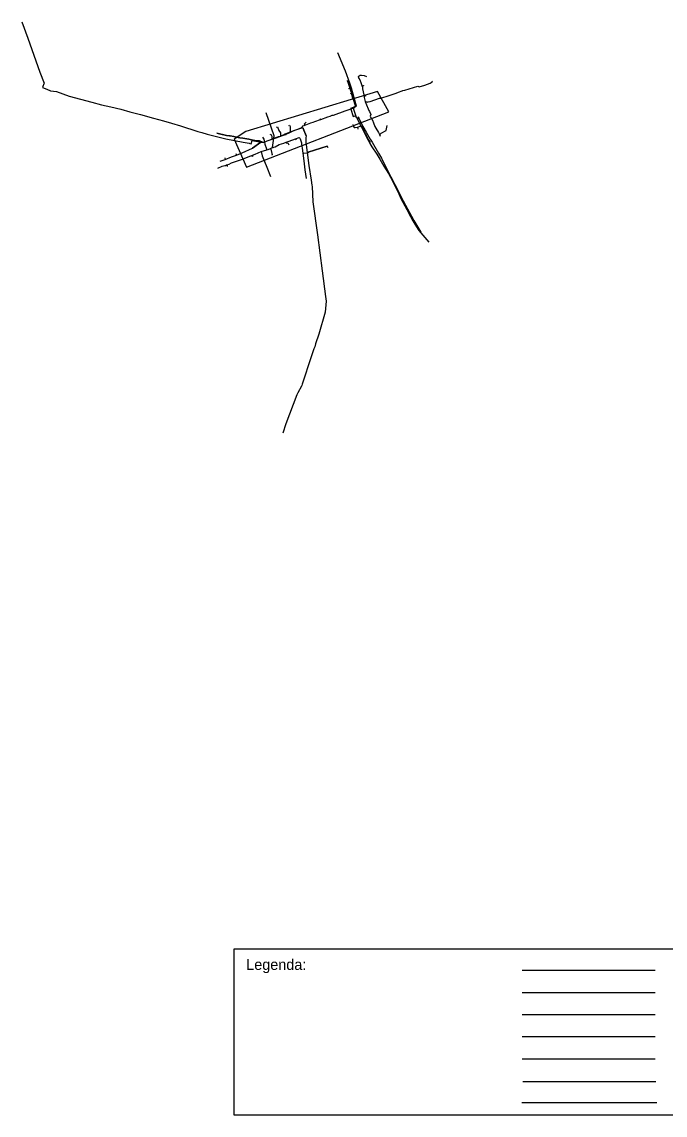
# Model space of a CAD drawing. Extents: x -703329 to -700959, y -1023502 to -1021827.
# Drawn here: x -703329 to -702432, y -1023352 to -1021827 of the extents above; entities that cross this region are included whole.
import ezdxf

# ---------------------------------------------------------------- set-up
doc = ezdxf.new("R2010")
doc.units = 0
for name, color, linetype in [('Vrstva 1', 7, 'Continuous'), ('Vrstva 2', 7, 'Continuous'), ('Vrstva 4', 7, 'Continuous'), ('Vrstva 63', 7, 'Continuous')]:
    doc.layers.add(name, color=color, linetype=linetype)

msp = doc.modelspace()

# ---------------------------------------------------------------- linework, layer by layer
at = {"layer": 'Vrstva 1'}
for p, q in [((-702631.5, -1023149.8), (-702446.1, -1023149.8)), ((-702631.5, -1023180.6), (-702446.1, -1023180.6)), ((-702631.5, -1023211.3), (-702446.1, -1023211.3)), ((-702631.5, -1023242), (-702446.1, -1023242)), ((-702631.5, -1023273.4), (-702446.1, -1023273.4)), ((-702630.5, -1023304.9), (-702445.1, -1023304.9)), ((-702631.7, -1023334.3), (-702443.7, -1023334.3))]:
    msp.add_line(p, q, dxfattribs=at)
for points in [[(-703328.6, -1021827.1), (-703320.4, -1021850), (-703303.8, -1021897.1), (-703297.8, -1021912.8), (-703298, -1021913.4), (-703299.6, -1021917.1), (-703300.1, -1021918.5), (-703293.9, -1021921), (-703288.7, -1021923.3), (-703280.4, -1021924.1), (-703262.9, -1021930.5), (-703231.3, -1021939.3), (-703217.5, -1021942.7), (-703204.7, -1021945.5), (-703190.7, -1021948.9), (-703178, -1021952.5), (-703172.5, -1021954.1), (-703163.3, -1021956.5), (-703145, -1021961.4), (-703131.4, -1021965.2), (-703119.9, -1021968.3), (-703107.6, -1021972.3), (-703083.5, -1021979.9), (-703077.9, -1021981.4), (-703070.4, -1021983.5), (-703057.2, -1021987.1), (-703044.3, -1021990), (-703032.5, -1021992.5), (-703020.3, -1021994.8), (-703011.7, -1021996.5)], [(-702859.8, -1021903.5), (-702857.1, -1021901.2), (-702855.5, -1021901.3), (-702851.6, -1021901.9), (-702848.5, -1021903.2)], [(-702859.8, -1021903.5), (-702859.2, -1021905.9), (-702857.5, -1021907.9), (-702856.1, -1021911.8), (-702855.9, -1021912.9), (-702854.8, -1021915.9), (-702854.7, -1021916.3)], [(-702875.2, -1021909.1), (-702873.9, -1021912.8), (-702872.1, -1021918.2), (-702871.5, -1021919.8), (-702870.5, -1021923), (-702869.2, -1021926.6)], [(-702873.9, -1021912.8), (-702872.1, -1021918.2)], [(-702871.5, -1021919.8), (-702870.5, -1021923)], [(-702855.9, -1021912.9), (-702854.8, -1021915.9)], [(-702854.7, -1021916.3), (-702852.8, -1021915.7), (-702851.9, -1021916.1)], [(-702854.7, -1021916.3), (-702854.1, -1021918.2), (-702854.1, -1021920.4), (-702852.1, -1021928.9), (-702851.9, -1021930.3), (-702851.8, -1021930.8)], [(-702848, -1021938.4), (-702846.7, -1021938.9), (-702845.8, -1021938.8), (-702843, -1021938), (-702830.3, -1021933.6), (-702828.2, -1021933.3), (-702816.9, -1021929.8), (-702806.9, -1021926.6), (-702803.7, -1021925), (-702798.6, -1021923.5), (-702797.5, -1021922.8), (-702795.1, -1021922.5), (-702776.6, -1021917), (-702775, -1021917.6), (-702767.2, -1021915.4), (-702759.6, -1021912.6), (-702756.7, -1021910.7), (-702756.5, -1021910.6), (-702756.8, -1021909.7)], [(-702912.3, -1021963.2), (-702911.9, -1021963.2), (-702902.2, -1021959.6), (-702898.9, -1021958.5), (-702897, -1021957.8), (-702896, -1021957), (-702894.5, -1021957), (-702878, -1021951.2), (-702864.7, -1021946.5), (-702863.6, -1021944.4), (-702866.3, -1021935.5)], [(-702870.5, -1021927), (-702869.2, -1021926.6)], [(-702866.3, -1021935.5), (-702867.2, -1021933.5), (-702868.1, -1021930.2), (-702869.2, -1021926.6)], [(-702868.1, -1021930.2), (-702867.2, -1021933.5)], [(-702851.8, -1021930.8), (-702848.6, -1021929.8)], [(-702851.8, -1021930.8), (-702851.6, -1021932.5), (-702850, -1021938.1)], [(-702850, -1021938.1), (-702849.5, -1021940.3), (-702845, -1021950.5), (-702844.2, -1021952.1), (-702842.4, -1021956.3), (-702843.3, -1021958.5), (-702842.6, -1021960.2), (-702841.9, -1021960.8)], [(-702850, -1021938.1), (-702848, -1021938.4)], [(-702849.5, -1021940.3), (-702845, -1021950.5)], [(-702934.1, -1021971.1), (-702934.8, -1021969.5), (-702932.5, -1021967.1)], [(-702934.1, -1021971.1), (-702932.8, -1021970.6), (-702925.8, -1021968.1), (-702922.6, -1021967), (-702920.5, -1021966.2), (-702912.3, -1021963.2)], [(-702922.6, -1021967), (-702920.5, -1021966.2)], [(-702912.9, -1021961.7), (-702912.3, -1021963.2)], [(-702902.2, -1021959.6), (-702898.9, -1021958.5)], [(-702841.9, -1021960.8), (-702841.2, -1021960.7)], [(-702841.9, -1021960.8), (-702840.2, -1021964.1)], [(-702841.9, -1021960.8), (-702840.2, -1021964.1), (-702838.5, -1021967.8), (-702836.5, -1021972.8), (-702834.1, -1021977.7), (-702832.8, -1021979.1), (-702831.5, -1021981.3), (-702830.4, -1021984.4)], [(-703054.9, -1021983), (-703056.8, -1021982.4)], [(-703056.8, -1021982.4), (-703054.9, -1021983)], [(-703049.6, -1021984.3), (-703054.9, -1021983)], [(-703054.9, -1021983), (-703049.6, -1021984.3)], [(-703049.6, -1021984.3), (-703049.4, -1021983.4)], [(-702986.6, -1021993.1), (-702985.4, -1021992.5), (-702980, -1021990.5), (-702974.4, -1021988.6), (-702968.9, -1021986.8), (-702960.4, -1021983.7), (-702955.2, -1021981.2), (-702952.3, -1021979.8)], [(-702973.7, -1021973.8), (-702972.6, -1021973.4), (-702970.4, -1021978.6), (-702968.4, -1021981.7), (-702968.2, -1021986.3)], [(-702948.3, -1021978.3), (-702937.2, -1021974.2), (-702936.5, -1021975.8), (-702932.5, -1021986.1), (-702933.1, -1021989), (-702932.7, -1021994.8), (-702928.7, -1022027.6), (-702925.5, -1022048), (-702924.4, -1022054.9), (-702924.1, -1022056.7), (-702923.3, -1022078.1), (-702916.8, -1022124.2), (-702910.2, -1022174.3), (-702905.4, -1022210.2), (-702904.4, -1022216.6), (-702906.1, -1022232), (-702914.8, -1022262.8), (-702919.3, -1022276.1), (-702920.5, -1022280.2), (-702921.6, -1022283.3), (-702925.4, -1022294.4), (-702937.8, -1022332.5), (-702938.3, -1022334.1), (-702938.8, -1022335.4), (-702943.9, -1022344.7), (-702945.3, -1022347.2), (-702960.7, -1022387.9), (-702965.1, -1022400.9)], [(-702962.6, -1021983.8), (-702961.8, -1021983.4)], [(-702961.8, -1021983.4), (-702955.2, -1021980.8)], [(-702961.8, -1021983.4), (-702961.2, -1021984.9)], [(-702956.7, -1021971.6), (-702955.6, -1021971.2), (-702954.8, -1021973.2), (-702954.8, -1021976.3), (-702954.7, -1021978.5), (-702955.2, -1021980.8)], [(-702955.2, -1021980.8), (-702949.7, -1021978.6), (-702945.6, -1021977), (-702939.4, -1021975), (-702937.6, -1021973.7), (-702937.4, -1021972.5), (-702937.3, -1021972.2), (-702935.4, -1021971.6), (-702934.1, -1021971.1)], [(-702955.2, -1021980.8), (-702949.7, -1021978.6)], [(-702952.3, -1021979.8), (-702948.3, -1021978.3)], [(-702932.5, -1021986.1), (-702936.5, -1021975.8)], [(-702934.1, -1021971.1), (-702935.4, -1021971.6)], [(-702932.8, -1021970.6), (-702934.1, -1021971.1)], [(-702867.5, -1021970.1), (-702866.7, -1021972), (-702865.7, -1021974.2), (-702864.1, -1021974.5), (-702860.7, -1021974.1)], [(-702860.7, -1021974.1), (-702855.8, -1021972.1)], [(-702860.7, -1021974.1), (-702860.3, -1021976.6)], [(-702855.8, -1021972.1), (-702845.2, -1021992.5), (-702843.2, -1021995.4)], [(-702831.5, -1021981.3), (-702830.4, -1021984.4)], [(-702830.4, -1021984.4), (-702829, -1021983.4), (-702827.8, -1021982.4), (-702820.8, -1021978.5), (-702819.7, -1021971.6)], [(-703039.4, -1021986), (-703043.4, -1021985.4), (-703049.1, -1021984.4), (-703049.6, -1021984.3)], [(-703049.6, -1021984.3), (-703049.1, -1021984.4), (-703043.4, -1021985.4), (-703039.4, -1021986)], [(-703039.4, -1021986), (-703039.2, -1021985.3)], [(-703029.5, -1021987.9), (-703033.1, -1021987.2), (-703038.4, -1021986.2), (-703039.4, -1021986)], [(-703039.4, -1021986), (-703038.4, -1021986.2), (-703033.1, -1021987.2), (-703029.5, -1021987.9)], [(-703029.6, -1022012.9), (-703021.4, -1022009.6), (-703007.3, -1022003.4), (-702995.4, -1021995), (-702993.5, -1021995)], [(-703029.5, -1021987.9), (-703029.4, -1021987.1)], [(-703029.5, -1021987.9), (-703024.7, -1021988.7), (-703020.7, -1021989.4), (-703015.3, -1021990.4)], [(-703015.3, -1021990.4), (-703020.7, -1021989.4), (-703024.7, -1021988.7), (-703029.5, -1021987.9)], [(-703015.3, -1021990.4), (-703015.1, -1021989.6)], [(-703015.3, -1021990.4), (-703012.4, -1021990.9), (-703008.4, -1021991.7), (-703001.5, -1021993), (-702997.6, -1021992.8), (-702993.5, -1021995)], [(-702993.5, -1021995), (-702997.6, -1021992.8), (-703001.5, -1021993), (-703008.4, -1021991.7), (-703012.4, -1021990.9), (-703015.3, -1021990.4)], [(-703011.7, -1021996.5), (-703011, -1021996.6)], [(-703011, -1021996.6), (-703009.3, -1021997), (-703007.8, -1021992.4), (-703006.3, -1021992.6)], [(-702995.4, -1021995), (-703007.3, -1022003.4)], [(-703006.3, -1021992.6), (-703005.5, -1021992.8)], [(-703005.5, -1021992.8), (-702996.9, -1021994.4), (-702991.6, -1021995.2), (-702986.6, -1021993.1)], [(-702993.5, -1021995), (-702992.9, -1021995.2), (-702992.3, -1021995)], [(-702993.3, -1021987.9), (-702991.5, -1021990.6), (-702990.3, -1021995)], [(-702992.3, -1021995), (-702990.7, -1021995)], [(-702990.7, -1021995), (-702990.3, -1021995)], [(-702990.7, -1021995), (-702990.1, -1021997.8), (-702987.7, -1022004), (-702987.2, -1022005.5)], [(-702990.3, -1021995), (-702987.6, -1021993.6), (-702986.8, -1021993.2), (-702984, -1021991.9), (-702980.5, -1021990.6)], [(-702990.3, -1021995), (-702987.6, -1021993.6), (-702986.8, -1021993.2)], [(-702990.1, -1021997.8), (-702987.7, -1022004)], [(-702982.5, -1021984.1), (-702981.5, -1021983.7), (-702980.5, -1021986.4), (-702980.5, -1021990.6)], [(-702980.5, -1021990.6), (-702976.4, -1021989), (-702973.2, -1021988), (-702970.8, -1021987.2)], [(-702975.6, -1022001.4), (-702970.1, -1021998.3), (-702963.5, -1021996.1)], [(-702970.8, -1021987.2), (-702968.2, -1021986.3)], [(-702968.2, -1021986.3), (-702966.3, -1021985.6), (-702963, -1021984.1), (-702962.6, -1021983.8)], [(-702968.2, -1021986.3), (-702966.3, -1021985.6), (-702963, -1021984.1)], [(-702963.5, -1021996.1), (-702960.1, -1021994.7)], [(-702960.1, -1021994.7), (-702956.1, -1021993.5), (-702947.2, -1021990.3)], [(-702960.1, -1021994.7), (-702959.5, -1021996.3), (-702957.8, -1021995.7), (-702956.7, -1021998.6)], [(-702947.2, -1021990.3), (-702942, -1021988.3), (-702941.1, -1021989.1), (-702940.8, -1021990.2), (-702939, -1021995.9), (-702938.9, -1021997.7), (-702938, -1022003.4), (-702937.1, -1022010.4)], [(-702947.2, -1021990.3), (-702946.7, -1021991.6)], [(-702938.9, -1021997.7), (-702938, -1022003.4)], [(-702830.4, -1021984.4), (-702829.2, -1021986.5)], [(-703045.1, -1022018.9), (-703036.6, -1022015.5), (-703029.6, -1022012.9)], [(-703043.3, -1022026.7), (-703039.7, -1022025.5), (-703036.3, -1022023.8), (-703022.7, -1022019), (-703009.7, -1022013.8), (-703007, -1022012.8)], [(-703030.6, -1022010.7), (-703029.6, -1022012.9)], [(-703007.4, -1022015.4), (-703007.6, -1022014.5), (-703006.5, -1022014), (-703007, -1022012.8)], [(-703007, -1022012.8), (-703003.6, -1022011.4), (-702995, -1022008.1)], [(-702995, -1022008.1), (-702987.2, -1022005.5)], [(-702995, -1022008.1), (-702994.5, -1022009.6), (-702993.6, -1022014), (-702990.7, -1022022), (-702987.4, -1022029.8), (-702982, -1022042.7)], [(-702987.2, -1022005.5), (-702985.4, -1022004.9), (-702982.2, -1022003.7)], [(-702982.2, -1022003.7), (-702980.1, -1022002.7), (-702978.2, -1022002.3), (-702977.4, -1022002)], [(-702982.2, -1022003.7), (-702981.8, -1022004.8), (-702979.6, -1022012.6), (-702980.6, -1022013)], [(-702977.6, -1022001.4), (-702977.4, -1022002)], [(-702977.4, -1022002), (-702975.6, -1022001.4)], [(-702937.1, -1022010.4), (-702935.7, -1022010.3), (-702931.2, -1022009.8), (-702929.6, -1022009.6)], [(-702937.1, -1022010.4), (-702935.7, -1022020.8), (-702934.4, -1022033.5), (-702932.6, -1022045.5)], [(-702935.7, -1022010.3), (-702931.2, -1022009.8)], [(-702902.3, -1022002.4), (-702903.2, -1022000.3), (-702929.7, -1022008.8), (-702929.6, -1022009.6)], [(-702929.6, -1022009.6), (-702929.7, -1022008.8), (-702903.2, -1022000.3), (-702902.3, -1022002.4)], [(-703055.6, -1022031), (-703049.3, -1022028.5), (-703045.9, -1022027.5), (-703044.7, -1022027.2), (-703043.3, -1022026.7)], [(-703052.5, -1022021.6), (-703045.1, -1022018.9)], [(-703045.9, -1022016.5), (-703045.1, -1022018.9)], [(-703043.3, -1022026.7), (-703042.7, -1022028.1), (-703042.5, -1022028.8), (-703042.7, -1022028.9)]]:
    msp.add_lwpolyline(points, dxfattribs=at)
msp.add_lwpolyline([(-703033, -1023119.8), (-701813, -1023119.8), (-701813, -1023351.8), (-703033, -1023351.8)], close=True, dxfattribs=at)
at = {"layer": 'Vrstva 2'}
for points in [[(-702888.8, -1021869.8), (-702877.9, -1021895.6), (-702872.1, -1021911.9)], [(-702875.3, -1021908.6), (-702873.9, -1021912.5), (-702871.5, -1021919.4)], [(-702873.6, -1021920.1), (-702871.5, -1021919.4)], [(-702872.1, -1021911.9), (-702869.9, -1021918.9), (-702862.8, -1021944), (-702862.5, -1021944.6), (-702863.9, -1021945)], [(-702871.5, -1021919.4), (-702863.3, -1021944.2), (-702863.6, -1021944.6), (-702863.9, -1021945)], [(-702866.1, -1021946), (-702870.8, -1021947.9), (-702870.4, -1021948.9), (-702867.1, -1021959), (-702867, -1021959.3), (-702864.1, -1021958.3), (-702861.4, -1021961.7), (-702858.8, -1021966.8), (-702855.2, -1021973.9), (-702850.9, -1021982.2), (-702845.8, -1021992), (-702845.4, -1021992.8), (-702844.1, -1021995.9), (-702843.8, -1021996.7), (-702840.8, -1022001.2), (-702834, -1022011.7), (-702829.9, -1022018.6), (-702824, -1022028.3), (-702817.8, -1022038.4), (-702814.9, -1022043.5), (-702804.2, -1022064.7), (-702800.9, -1022072.3), (-702797.8, -1022078.4), (-702792.2, -1022088.8), (-702789.7, -1022093.4), (-702783.9, -1022104.5), (-702783.4, -1022105.3), (-702775.3, -1022118.2), (-702761.6, -1022134.5)], [(-702866.1, -1021946), (-702867, -1021947), (-702866.9, -1021947.5), (-702863.3, -1021958.4), (-702862.7, -1021960), (-702860.3, -1021961.2), (-702858.9, -1021962), (-702858.4, -1021962.5)], [(-702866.1, -1021946), (-702864.5, -1021945.2), (-702863.9, -1021945)], [(-702866.1, -1021946), (-702864.5, -1021945.3), (-702863.9, -1021945.1), (-702863.9, -1021945)], [(-702859.5, -1021959.6), (-702859.9, -1021959.8), (-702858.4, -1021962.5)], [(-702858.4, -1021962.5), (-702853.4, -1021973), (-702848.7, -1021981), (-702843.4, -1021990.7), (-702840.4, -1021995), (-702831.6, -1022010.2), (-702827.5, -1022017.1), (-702817.1, -1022038), (-702814.5, -1022043.2), (-702803.3, -1022064.4), (-702799.8, -1022071.8), (-702788.5, -1022092.9), (-702785.6, -1022098.2), (-702782.6, -1022104), (-702772.7, -1022120.5)]]:
    msp.add_lwpolyline(points, dxfattribs=at)
at = {"layer": 'Vrstva 4'}
msp.add_lwpolyline([(-702979.2, -1022002.1), (-702976.9, -1021985.9), (-702988, -1021954.1)], dxfattribs=at)
at = {"layer": 'Vrstva 63'}
msp.add_lwpolyline([(-703033, -1021990.5), (-703015.7, -1022029.8), (-702817.3, -1021952.8), (-702833, -1021924.2), (-703016.3, -1021980), (-703033, -1021990.5)], close=True, dxfattribs=at)

# ---------------------------------------------------------------- texts
at = {"layer": 'Vrstva 1'}
msp.add_text('Legenda:', height=15, dxfattribs=at).set_placement((-703015.9, -1023149.3))

doc.saveas('drawing.dxf')
